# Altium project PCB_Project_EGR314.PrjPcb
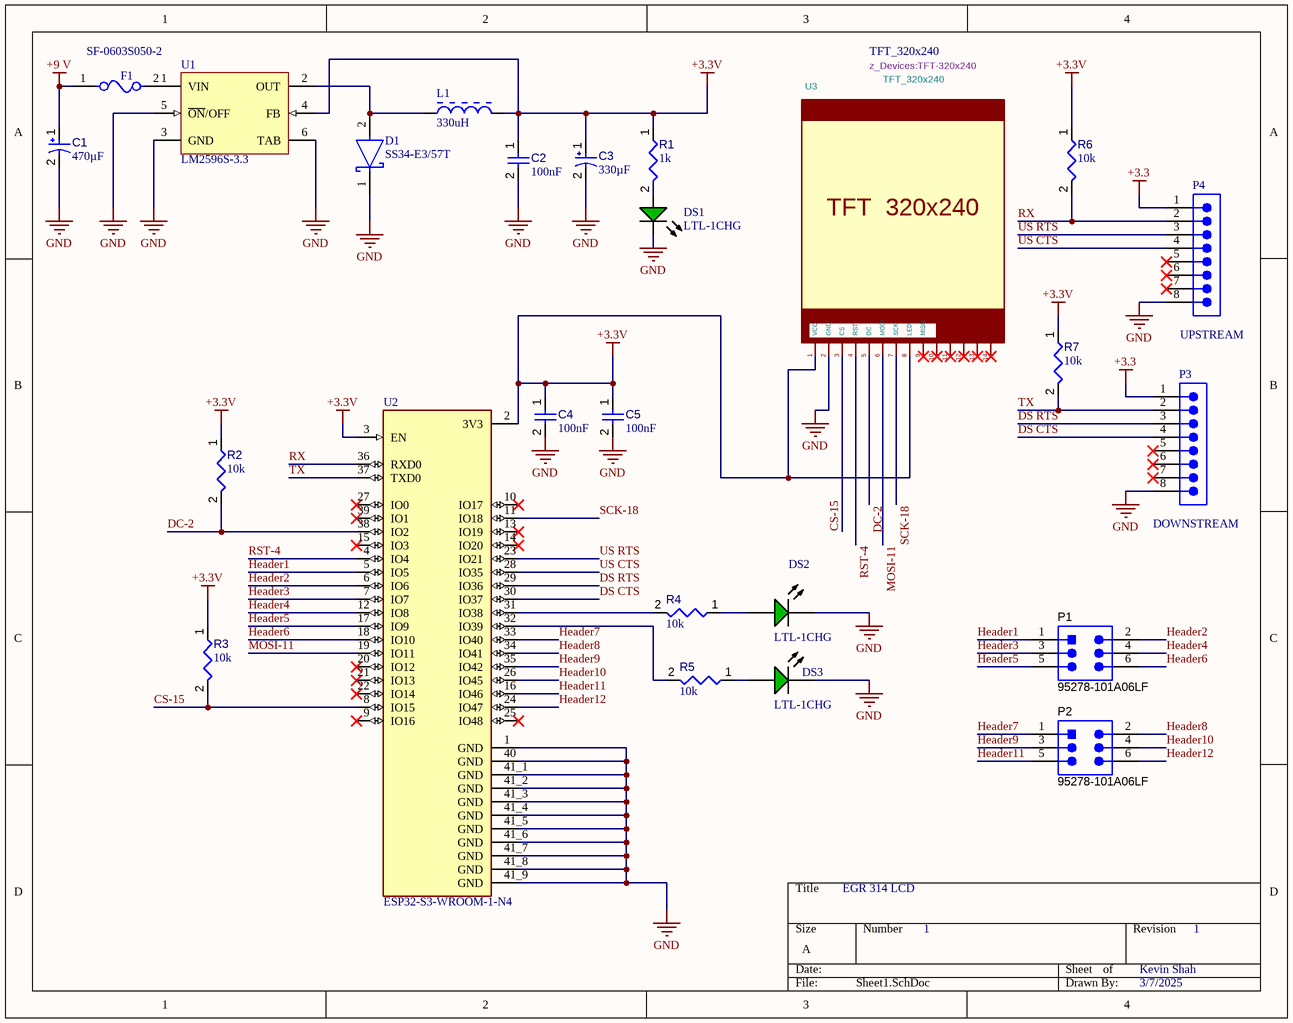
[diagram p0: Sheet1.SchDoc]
1 sheet, 25 parts. Net scope: global (net labels, ports and power ports of the same name join across sheets).
Board files: PCB1.PcbDoc, triak.PcbDoc

## Sheet Sheet1.SchDoc
size A; SheetNumber: 1; SheetTotal: 1

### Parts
C1  value 470µF  [CAPPR65-500-2000X1000X2200]  (hidden comment: ECA-1HM471)
C2  value 100nF  [CAPC0402(1005)60_L]  (hidden comment: Capacitor 100nF +/-20% 10V 0402)
C3  value 330µF  [PNSC-6TPF220M5L]  (hidden comment: Capacitor 330µF +/-20% 6.3V D3)
C4  value 100nF  [CAPC0402(1005)60_L]  (hidden comment: Capacitor 100nF +/-20% 10V 0402)
C5  value 100nF  [CAPC0402(1005)60_L]  (hidden comment: Capacitor 100nF +/-20% 10V 0402)
D1  SS34-E3/57T  [FP-95402-MFG]
DS1  LTL-1CHG  [LTST-LTL-1CHG-2]
DS2  LTL-1CHG  [LTST-LTL-1CHG-2]
DS3  LTL-1CHG  [LTST-LTL-1CHG-2]
F1  SF-0603S050-2  [FP-SF-0603S-MFG]
L1  330uH  [BOUR-SRN3015-2_V]
P1  95278-101A06LF  [AMPM-95278-101A06LF_V]
P2  95278-101A06LF  [AMPM-95278-101A06LF_V]
P3  DOWNSTREAM  [61300811121]
P4  UPSTREAM  [61300811121]
R1  value 1k  [RESA60-630X240]  (hidden comment: MFR-25FBF52-1K)
R2  value 10k  [RESC1005X40X25ML05T05]  (hidden comment: Resistor 10k +/-1% 0402 63 mW)
R3  value 10k  [RESC1005X40X25ML05T05]  (hidden comment: Resistor 10k +/-1% 0402 63 mW)
R4  value 10k  [RESC1005X40X25ML05T05]  (hidden comment: Resistor 10k +/-1% 0402 63 mW)
R5  value 10k  [RESC1005X40X25ML05T05]  (hidden comment: Resistor 10k +/-1% 0402 63 mW)
R6  value 10k  [RESC1005X40X25ML05T05]  (hidden comment: Resistor 10k +/-1% 0402 63 mW)
R7  value 10k  [RESC1005X40X25ML05T05]  (hidden comment: Resistor 10k +/-1% 0402 63 mW)
U1  LM2596S-3.3  [KTT0005B_N]
U2  ESP32-S3-WROOM-1-N4  [XCVR_ESP32-S3-WROOM-1U-N4]
U3  TFT_320x240  Footprint: z_Devices:TFT-320x240  [PCBComponent_1]

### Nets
+3.3: P3.1 P4.1
+3.3V: C2.1 C3.1 C4.1 C5.1 L1.2 R1.1 R2.1 R3.1 R6.1 R7.1 U1.4(FB) U2.2(3V3) U2.3(EN) U3.1(VCC) U3.8(LED)
+9 V: C1.1 F1.1
GND: C1.2 C2.2 C3.2 C4.2 C5.2 D1.1(C) DS1.2(K) DS2.2(K) DS3.2(K) P3.8 P4.8 U1.3(GND) U1.5(~{ON}/OFF) U1.6(TAB) U2.1(GND) U2.40(GND) U2.41_1(GND) U2.41_2(GND) U2.41_3(GND) U2.41_4(GND) U2.41_5(GND) U2.41_6(GND) U2.41_7(GND) U2.41_8(GND) U2.41_9(GND) U3.2(GND)
CS-15: R3.2 U2.8(IO15) U3.3(CS)
DC-2: R2.2 U2.38(IO2) U3.5(DC)
DS CTS: P3.4 U2.30(IO37)
DS RTS: P3.3 U2.29(IO36)
Header1: P1.1 U2.5(IO5)
Header2: P1.2 U2.6(IO6)
Header3: P1.3 U2.7(IO7)
Header4: P1.4 U2.12(IO8)
Header5: P1.5 U2.17(IO9)
Header6: P1.6 U2.18(IO10)
Header7: P2.1 U2.33(IO40)
Header8: P2.2 U2.34(IO41)
Header9: P2.3 U2.35(IO42)
Header10: P2.4 U2.26(IO45)
Header11: P2.5 U2.16(IO46)
Header12: P2.6 U2.24(IO47)
MOSI-11: U2.19(IO11) U3.6(MOSI)
RST-4: U2.4(IO4) U3.4(RST)
RX: P4.2 R6.2 U2.36(RXD0)
SCK-18: U2.11(IO18) U3.7(SCK)
TX: P3.2 R7.2 U2.37(TXD0)
US CTS: P4.4 U2.28(IO35)
US RTS: P4.3 U2.23(IO21)
NetD1_2: D1.2(A) L1.1 U1.2(OUT)
NetDS1_1: DS1.1(A) R1.2
NetDS2_1: DS2.1(A) R4.1
NetDS3_1: DS3.1(A) R5.1
NetR4_2: R4.2 U2.31(IO38)
NetR5_2: R5.2 U2.32(IO39)

Not connected (* = marked no-connect by the designer): F1 2; P3 5* 6* 7*; P4 5* 6* 7*; U1 1(VIN); U2 9(IO16)* 10(IO17)* 13(IO19)* 14(IO20)* 15(IO3)* 20(IO12)* 21(IO13)* 22(IO14)* 25(IO48)* 27(IO0)* 39(IO1)*; U3 9(MISO)* 10* 11* 12* 13* 14*

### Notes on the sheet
- EGR 314 LCD
- 1
- Kevin Shah
- 3/7/2025

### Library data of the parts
C1 = CMP-001-00032-8: Aluminum Electrolytic Capacitor, 470 uF, +/- 20%, 50 V, -40 to 85 degC, 2-Pin THD, RoHS, Bulk; Manufacturer: Panasonic; Ripple Current: 650mA; Voltage Rating: 50V
C2 C4 C5 = CMP-001-00061-3: Chip Capacitor, 100nF +/-20%, 10V, 0402, Thickness 0.6 mm; Tolerance: 20%
C3 = CMP-001-00058-3: Molded Tantalum Polymer Capacitor, 330 uF, +/- 20%, 6.3 V, -55 to 105 degC, 2-Pin SMD, RoHS, Tape and Reel
D1 = CMP-02539-000012-1: DIODE SCHOTTKY 40V 3A DO214AB; Manufacturer: Vishay; Max Junction Temp: +150°C; Peak Reverse Current: 0.5mA; Max Surge Forward Current: 100A; Standoff Height: 0mm
DS1-DS3 = CMP-007-00019-2: LED Uni-Color Green, 100 mW, 30 mA, -55 to 100 degC, 2-Pin THD, RoHS, Bulk; Manufacturer: Lite-On; Power: 100mW; Forward Voltage: 2.6V; Forward Current: 30mA; Nominal Vf: 2.1V; Lens Style: Dome; Viewing Angle: 60degrees; Luminous Intensity: 12.6mcd
F1 = CMP-07399-000004-1: FUSE BOARD MNT 500MA 50VDC 0603; Manufacturer: Bourns Inc.; Fuse I2T: 0.009A2Sec; Fuse Current: 0.5A; Fuse Interrupt Ac Current: 50A; Max Fuse Ac Voltage: 35V; Resistance: 232mΩ; Fuse Blow Speed: Slow; Value: 232mΩ; Max Fuse Dc Voltage: 50V
L1 = CMP-0007-00002-1: Semi-shielded Power Inductor, 33 uH, +/- 20%, 0.5 A, -40 to 125 degC, 3 x 3 x 1.5 mm SMD, RoHS and Halogen Free, Tape and Reel; PartNumber: SRN3015-330M; Manufacturer: Bourns; DCR Max: 0.959 Ohm; Resistance to Solder Heat: +260 degC for 10 sec.; Inductance: 33 uH; Isat: 0.46 A; Rated current: 0.5 A; SRF Min: 22 MHz; Inductance tolerance: +/- 20%
P1 P2 = CMP-002-00024-2: Male Header, Pitch 2.54 mm, 2 x 3 Position, Height 14.4 mm, RoHS, Tape and Reel; Manufacturer: Amphenol
P3 P4 = CMP-1502-01076-3: NexarPartId: 32855533; Connector Type: Male Pin; Number of Contacts: 8; Voltage Rating: 250V; Current Rating: 3A; Contact Resistance: 20mΩ; Pitch: 2.54mm; Gender: Male
R1 = CMP-009-00048-4: Axial Resistor, 1 KOhm, +/- 1%, 250 mW, -55 to 155 degC, 2-Pin THD, RoHS, Bulk; Manufacturer: Yageo; Voltage Rating: 250V; Power: 250mW
R2-R7 = CMP-009-00019-5: Chip Resistor, 10 KOhm, +/- 1%, 63 mW, -55 to 155 degC, 0402 (1005 Metric); Power: 63mW; Voltage Rating: 50V
U1 = CMP-0069-00276-3: SIMPLE SWITCHER® Power Converter 150 KHz 3A Step-Down Voltage Regulator, 5-pin TO-263; Manufacturer: Texas Instruments; PowerWise: N; PackageTopMarking: NSUZXYTTE#*LM2596S*-3.3 P+
U2 = ESP32-S3-WROOM-1-N4: MF: {'manufacturer': u'Espressif Systems'}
